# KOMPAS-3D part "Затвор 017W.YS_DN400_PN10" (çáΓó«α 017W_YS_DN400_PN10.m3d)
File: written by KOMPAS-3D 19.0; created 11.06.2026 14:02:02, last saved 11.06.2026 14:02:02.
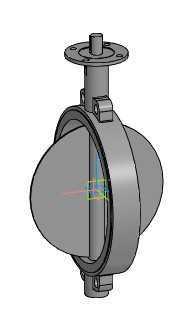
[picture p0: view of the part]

Document properties: Автор: Евгений; Полное имя файла: Z:\3.Личные\kachalov\001_3d для проектировщиков\x.x Тип 017W.Y(S) Затвор дисковый поворотный межфланцевый\_stp_Затвор 017W.YS_DN32-DN1200\Затвор 017W_YS_DN400_PN10.m3d

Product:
- Part/product: Затвор 017W.YS_DN400_PN10

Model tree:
1. Операция без истории:1  (labels: Затвор 017W.YS_DN400_PN10)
